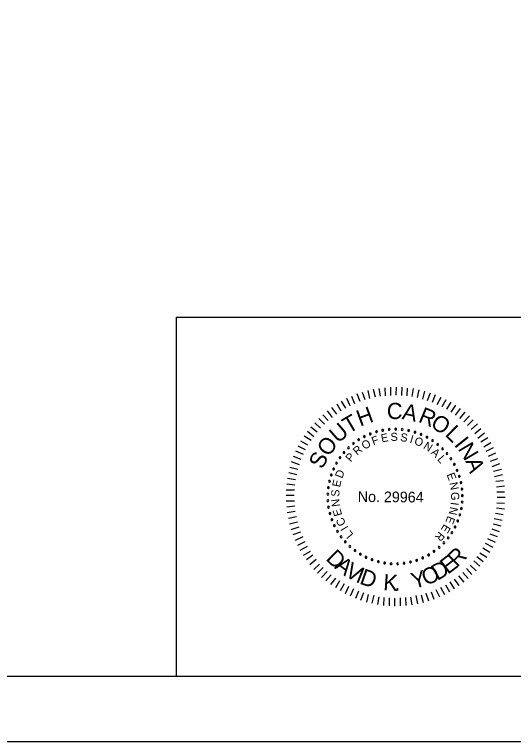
# Model space of a CAD drawing. Extents: x -121.2 to -24.9, y 6.4 to 65.7.
# Drawn here: x -64.11 to -53.92, y 6.35 to 21.19 of the extents above; entities that cross this region are included whole.
import ezdxf

# ---------------------------------------------------------------- set-up
doc = ezdxf.new("R2010")
doc.units = 0
for name, color, linetype in [('BR_BORDER LINES', 7, 'Continuous'), ('BR_TEXT', 7, 'Continuous'), ('Level 31', 7, 'Continuous')]:
    doc.layers.add(name, color=color, linetype=linetype)

msp = doc.modelspace()

# ---------------------------------------------------------------- linework, layer by layer
at = {"layer": 'BR_BORDER LINES'}
for p, q in [((-60.804, 15.017), (-46.496, 15.017)), ((-60.804, 7.683), (-60.804, 15.017)), ((-116.272, 7.683), (-26.496, 7.683))]:
    msp.add_line(p, q, dxfattribs=at)
at = {"layer": 'BR_TEXT'}
for p, q in [((-56.854, 13.352), (-56.89, 13.515)), ((-56.744, 13.379), (-56.782, 13.537)), ((-56.639, 13.398), (-56.663, 13.561)), ((-56.534, 13.409), (-56.544, 13.572)), ((-56.428, 13.415), (-56.427, 13.587)), ((-56.316, 13.421), (-56.315, 13.586)), ((-56.204, 13.413), (-56.198, 13.585)), ((-56.097, 13.405), (-56.084, 13.568)), ((-55.994, 13.393), (-55.965, 13.555)), ((-55.886, 13.372), (-55.848, 13.529)), ((-57.16, 13.247), (-57.223, 13.396)), ((-57.056, 13.292), (-57.112, 13.448)), ((-56.951, 13.326), (-57.009, 13.479)), ((-55.777, 13.343), (-55.734, 13.505)), ((-55.679, 13.315), (-55.62, 13.468)), ((-55.574, 13.28), (-55.515, 13.435)), ((-55.478, 13.233), (-55.403, 13.381)), ((-57.445, 13.092), (-57.526, 13.236)), ((-57.35, 13.155), (-57.432, 13.3)), ((-57.258, 13.202), (-57.328, 13.351)), ((-55.382, 13.187), (-55.298, 13.335)), ((-55.282, 13.138), (-55.196, 13.281)), ((-55.193, 13.073), (-55.103, 13.216)), ((-57.617, 12.967), (-57.724, 13.101)), ((-57.528, 13.035), (-57.632, 13.171)), ((-55.104, 13.015), (-55.007, 13.149)), ((-55.018, 12.946), (-54.909, 13.078)), ((-57.783, 12.829), (-57.901, 12.947)), ((-57.705, 12.902), (-57.816, 13.021)), ((-54.934, 12.879), (-54.818, 12.997)), ((-54.859, 12.805), (-54.743, 12.921)), ((-57.929, 12.663), (-58.061, 12.767)), ((-57.862, 12.747), (-57.978, 12.86)), ((-54.784, 12.722), (-54.657, 12.833)), ((-57.998, 12.574), (-58.13, 12.681)), ((-54.712, 12.636), (-54.587, 12.738)), ((-54.648, 12.547), (-54.517, 12.651)), ((-58.121, 12.399), (-58.264, 12.485)), ((-58.056, 12.497), (-58.2, 12.585)), ((-54.589, 12.468), (-54.449, 12.554)), ((-58.168, 12.308), (-58.318, 12.382)), ((-54.531, 12.37), (-54.388, 12.453)), ((-54.483, 12.278), (-54.329, 12.35)), ((-58.214, 12.21), (-58.367, 12.278)), ((-54.436, 12.179), (-54.284, 12.244)), ((-58.294, 12), (-58.458, 12.061)), ((-58.261, 12.107), (-58.416, 12.166)), ((-54.391, 12.075), (-54.24, 12.131)), ((-54.355, 11.968), (-54.202, 12.026)), ((-58.326, 11.904), (-58.489, 11.945)), ((-54.329, 11.871), (-54.168, 11.909)), ((-58.346, 11.792), (-58.512, 11.835)), ((-54.307, 11.759), (-54.146, 11.799)), ((-58.386, 11.587), (-58.551, 11.606)), ((-58.374, 11.696), (-58.536, 11.718)), ((-54.285, 11.663), (-54.127, 11.682)), ((-58.394, 11.481), (-58.566, 11.483)), ((-54.267, 11.553), (-54.105, 11.57)), ((-54.264, 11.447), (-54.103, 11.446)), ((-58.4, 11.372), (-58.567, 11.373)), ((-54.258, 11.338), (-54.095, 11.336)), ((-58.396, 11.257), (-58.568, 11.254)), ((-58.39, 11.154), (-58.555, 11.135)), ((-54.265, 11.223), (-54.105, 11.217)), ((-58.379, 11.044), (-58.542, 11.02)), ((-54.29, 11.011), (-54.132, 10.984)), ((-54.271, 11.12), (-54.109, 11.098)), ((-58.353, 10.939), (-58.52, 10.904)), ((-54.314, 10.905), (-54.154, 10.867)), ((-58.335, 10.826), (-58.498, 10.789)), ((-58.304, 10.728), (-58.469, 10.672)), ((-54.366, 10.695), (-54.213, 10.637)), ((-54.338, 10.793), (-54.178, 10.753)), ((-58.273, 10.625), (-58.429, 10.569)), ((-54.403, 10.593), (-54.253, 10.534)), ((-58.228, 10.526), (-58.382, 10.454)), ((-58.183, 10.429), (-58.335, 10.35)), ((-54.499, 10.399), (-54.346, 10.318)), ((-54.45, 10.495), (-54.3, 10.42)), ((-58.138, 10.331), (-58.283, 10.247)), ((-54.548, 10.301), (-54.407, 10.215)), ((-58.075, 10.232), (-58.22, 10.148)), ((-58.018, 10.153), (-58.152, 10.056)), ((-54.668, 10.126), (-54.539, 10.026)), ((-54.608, 10.203), (-54.469, 10.117)), ((-57.95, 10.064), (-58.084, 9.959)), ((-57.885, 9.974), (-58.002, 9.865)), ((-54.807, 9.948), (-54.682, 9.837)), ((-54.733, 10.037), (-54.61, 9.931)), ((-57.808, 9.904), (-57.927, 9.784)), ((-57.73, 9.824), (-57.844, 9.701)), ((-54.959, 9.801), (-54.846, 9.676)), ((-54.883, 9.88), (-54.77, 9.758)), ((-57.644, 9.754), (-57.753, 9.629)), ((-57.555, 9.685), (-57.662, 9.558)), ((-55.132, 9.665), (-55.037, 9.536)), ((-55.044, 9.733), (-54.938, 9.606)), ((-57.473, 9.627), (-57.557, 9.488)), ((-57.38, 9.567), (-57.464, 9.423)), ((-57.289, 9.513), (-57.361, 9.365)), ((-55.311, 9.55), (-55.228, 9.405)), ((-55.222, 9.608), (-55.134, 9.468)), ((-57.191, 9.467), (-57.256, 9.319)), ((-57.088, 9.42), (-57.147, 9.27)), ((-56.983, 9.387), (-57.044, 9.232)), ((-56.888, 9.354), (-56.925, 9.197)), ((-55.711, 9.377), (-55.655, 9.221)), ((-55.606, 9.408), (-55.55, 9.256)), ((-55.509, 9.453), (-55.437, 9.304)), ((-55.413, 9.498), (-55.331, 9.348)), ((-56.778, 9.335), (-56.818, 9.171)), ((-56.673, 9.305), (-56.699, 9.149)), ((-56.568, 9.292), (-56.58, 9.128)), ((-56.462, 9.285), (-56.464, 9.12)), ((-56.35, 9.277), (-56.352, 9.114)), ((-56.238, 9.283), (-56.235, 9.118)), ((-56.131, 9.289), (-56.121, 9.124)), ((-56.028, 9.299), (-56.001, 9.143)), ((-55.92, 9.328), (-55.884, 9.163)), ((-55.81, 9.346), (-55.77, 9.187))]:
    msp.add_line(p, q, dxfattribs=at)
for centre, start, end in [((-56.847, 12.632), 21.6807, 201.6807), ((-56.847, 12.632), 201.6807, 21.6807), ((-56.721, 12.674), 16.1422, 196.1422), ((-56.721, 12.674), 196.1422, 16.1422), ((-56.592, 12.705), 10.6038, 190.6038), ((-56.592, 12.705), 190.6038, 10.6038), ((-56.46, 12.723), 5.0653, 185.0653), ((-56.46, 12.723), 185.0653, 5.0653), ((-56.328, 12.728), 359.5268, 179.5268), ((-56.328, 12.728), 179.5268, 359.5268), ((-56.195, 12.72), 353.9884, 173.9884), ((-56.195, 12.72), 173.9884, 353.9884), ((-56.064, 12.699), 348.4499, 168.4499), ((-56.064, 12.699), 168.4499, 348.4499), ((-55.935, 12.666), 162.9114, 342.9114), ((-55.935, 12.666), 342.9114, 162.9114), ((-55.81, 12.621), 157.373, 337.373), ((-55.81, 12.621), 337.373, 157.373), ((-57.083, 12.511), 32.7576, 212.7576), ((-57.083, 12.511), 212.7576, 32.7576), ((-56.968, 12.577), 27.2191, 207.2191), ((-56.968, 12.577), 207.2191, 27.2191), ((-55.69, 12.564), 151.8345, 331.8345), ((-55.69, 12.564), 331.8345, 151.8345), ((-55.576, 12.495), 146.2961, 326.2961), ((-55.576, 12.495), 326.2961, 146.2961), ((-57.292, 12.347), 43.8345, 223.8345), ((-57.292, 12.347), 223.8345, 43.8345), ((-57.192, 12.434), 38.2961, 218.2961), ((-57.192, 12.434), 218.2961, 38.2961), ((-55.47, 12.416), 140.7576, 320.7576), ((-55.47, 12.416), 320.7576, 140.7576), ((-55.371, 12.327), 135.2191, 315.2191), ((-55.371, 12.327), 315.2191, 135.2191), ((-57.384, 12.25), 49.373, 229.373), ((-57.384, 12.25), 229.373, 49.373), ((-55.282, 12.229), 129.6807, 309.6807), ((-55.282, 12.229), 309.6807, 129.6807), ((-57.537, 12.033), 60.4499, 240.4499), ((-57.537, 12.033), 240.4499, 60.4499), ((-57.465, 12.145), 54.9114, 234.9114), ((-57.465, 12.145), 234.9114, 54.9114), ((-55.202, 12.122), 124.1422, 304.1422), ((-55.202, 12.122), 304.1422, 124.1422), ((-55.133, 12.009), 118.6038, 298.6038), ((-55.133, 12.009), 298.6038, 118.6038), ((-57.597, 11.915), 65.9884, 245.9884), ((-57.597, 11.915), 245.9884, 65.9884), ((-55.075, 11.889), 113.0653, 293.0653), ((-55.075, 11.889), 293.0653, 113.0653), ((-57.645, 11.791), 71.5268, 251.5268), ((-57.645, 11.791), 251.5268, 71.5268), ((-55.029, 11.764), 107.5268, 287.5268), ((-55.029, 11.764), 287.5268, 107.5268), ((-57.681, 11.663), 77.0653, 257.0653), ((-57.681, 11.663), 257.0653, 77.0653), ((-54.996, 11.636), 101.9884, 281.9884), ((-54.996, 11.636), 281.9884, 101.9884), ((-57.705, 11.532), 82.6038, 262.6038), ((-57.705, 11.532), 262.6038, 82.6038), ((-54.975, 11.504), 96.4499, 276.4499), ((-54.975, 11.504), 276.4499, 96.4499), ((-57.716, 11.4), 88.1422, 268.1422), ((-57.714, 11.267), 93.6807, 273.6807), ((-57.716, 11.4), 268.1422, 88.1422), ((-57.714, 11.267), 273.6807, 93.6807), ((-54.967, 11.372), 90.9114, 270.9114), ((-54.967, 11.372), 270.9114, 90.9114), ((-57.7, 11.135), 99.2191, 279.2191), ((-57.7, 11.135), 279.2191, 99.2191), ((-54.971, 11.239), 85.373, 265.373), ((-54.971, 11.239), 265.373, 85.373), ((-57.672, 11.005), 104.7576, 284.7576), ((-57.672, 11.005), 284.7576, 104.7576), ((-55.019, 10.978), 74.2961, 254.2961), ((-55.019, 10.978), 254.2961, 74.2961), ((-54.989, 11.107), 79.8345, 259.8345), ((-54.989, 11.107), 259.8345, 79.8345), ((-57.632, 10.878), 110.2961, 290.2961), ((-57.632, 10.878), 290.2961, 110.2961), ((-55.061, 10.852), 68.7576, 248.7576), ((-55.061, 10.852), 248.7576, 68.7576), ((-57.581, 10.756), 115.8345, 295.8345), ((-57.581, 10.756), 295.8345, 115.8345), ((-55.115, 10.731), 63.2191, 243.2191), ((-55.115, 10.731), 243.2191, 63.2191), ((-57.517, 10.639), 121.373, 301.373), ((-57.517, 10.639), 301.373, 121.373), ((-57.443, 10.529), 126.9114, 306.9114), ((-57.443, 10.529), 306.9114, 126.9114), ((-55.181, 10.615), 57.6807, 237.6807), ((-55.181, 10.615), 237.6807, 57.6807), ((-57.358, 10.426), 132.4499, 312.4499), ((-57.358, 10.426), 312.4499, 132.4499), ((-55.344, 10.406), 46.6038, 226.6038), ((-55.344, 10.406), 226.6038, 46.6038), ((-55.258, 10.507), 52.1422, 232.1422), ((-55.258, 10.507), 232.1422, 52.1422), ((-57.264, 10.333), 137.9884, 317.9884), ((-57.264, 10.333), 317.9884, 137.9884), ((-57.161, 10.248), 143.5268, 323.5268), ((-57.161, 10.248), 323.5268, 143.5268), ((-55.545, 10.232), 35.5268, 215.5268), ((-55.545, 10.232), 215.5268, 35.5268), ((-55.44, 10.314), 41.0653, 221.0653), ((-55.44, 10.314), 221.0653, 41.0653), ((-57.051, 10.174), 149.0653, 329.0653), ((-57.051, 10.174), 329.0653, 149.0653), ((-56.934, 10.112), 154.6038, 334.6038), ((-56.934, 10.112), 334.6038, 154.6038), ((-55.775, 10.1), 24.4499, 204.4499), ((-55.775, 10.1), 204.4499, 24.4499), ((-55.657, 10.16), 29.9884, 209.9884), ((-55.657, 10.16), 209.9884, 29.9884), ((-56.811, 10.06), 160.1422, 340.1422), ((-56.811, 10.06), 340.1422, 160.1422), ((-56.684, 10.021), 345.6807, 165.6807), ((-56.684, 10.021), 165.6807, 345.6807), ((-56.554, 9.994), 351.2191, 171.2191), ((-56.554, 9.994), 171.2191, 351.2191), ((-56.422, 9.98), 356.7576, 176.7576), ((-56.422, 9.98), 176.7576, 356.7576), ((-56.289, 9.978), 2.2961, 182.2961), ((-56.289, 9.978), 182.2961, 2.2961), ((-56.157, 9.99), 7.8345, 187.8345), ((-56.157, 9.99), 187.8345, 7.8345), ((-56.026, 10.014), 13.373, 193.373), ((-56.026, 10.014), 193.373, 13.373), ((-55.899, 10.051), 18.9114, 198.9114), ((-55.899, 10.051), 198.9114, 18.9114)]:
    msp.add_arc(centre, 0.0187, start, end, dxfattribs=at)
at = {"layer": 'Level 31'}
msp.add_lwpolyline([(-121.161, 6.35), (-25.161, 6.35), (-25.161, 65.017), (-121.161, 65.017)], close=True, dxfattribs=at)

# ---------------------------------------------------------------- texts
at = {"layer": 'BR_TEXT'}
for s, height, rotation, p in [('C', 0.331, 359.5482, (-56.51, 12.935)), ('A', 0.331, 348.1981, (-56.213, 12.937)), ('H', 0.331, 20.3637, (-57.055, 12.779)), ('R', 0.331, 337.4344, (-55.884, 12.884)), ('T', 0.331, 30.4992, (-57.29, 12.626)), ('O', 0.33, 326.5869, (-55.638, 12.786)), ('U', 0.331, 40.8022, (-57.506, 12.426)), ('L', 0.331, 315.9488, (-55.338, 12.605)), ('E', 0.166, 11.4103, (-56.611, 12.456)), ('S', 0.166, 2.208, (-56.431, 12.485)), ('S', 0.166, 352.6608, (-56.241, 12.485)), ('O', 0.331, 52.0267, (-57.705, 12.149)), ('O', 0.166, 30.8477, (-56.965, 12.302)), ('F', 0.166, 20.6127, (-56.785, 12.398)), ('I', 0.166, 343.1136, (-56.053, 12.453)), ('O', 0.166, 338.4392, (-55.964, 12.426)), ('N', 0.166, 328.2042, (-55.778, 12.342)), ('I', 0.331, 308.6613, (-55.148, 12.407)), ('R', 0.166, 40.3949, (-57.115, 12.185)), ('N', 0.331, 300.7037, (-55.066, 12.329)), ('S', 0.33, 63.2511, (-57.826, 11.894)), ('P', 0.166, 49.9421, (-57.243, 12.045)), ('A', 0.166, 318.657, (-55.621, 12.235)), ('L', 0.166, 309.4546, (-55.488, 12.109)), ('A', 0.331, 289.4792, (-54.908, 12.081)), ('D', 0.166, 69.0364, (-57.421, 11.711)), ('E', 0.166, 291.049, (-55.291, 11.801)), ('E', 0.166, 78.2388, (-57.466, 11.533)), ('N', 0.166, 281.8466, (-55.232, 11.628)), ('S', 0.166, 87.786, (-57.481, 11.344)), ('No. 29964', 0.218, 359.5268, (-57.104, 11.241)), ('G', 0.166, 272.2995, (-55.201, 11.441)), ('N', 0.166, 97.3332, (-57.464, 11.154)), ('N', 0.166, 257.7339, (-55.214, 11.151)), ('I', 0.166, 262.4084, (-55.202, 11.244)), ('E', 0.166, 106.5355, (-57.419, 10.977)), ('C', 0.166, 116.4266, (-57.339, 10.797)), ('E', 0.166, 248.1867, (-55.262, 10.968)), ('I', 0.166, 121.1011, (-57.291, 10.717)), ('E', 0.166, 238.9844, (-55.337, 10.8)), ('L', 0.166, 129.9595, (-57.183, 10.578)), ('R', 0.166, 229.782, (-55.437, 10.647)), ('D', 0.329, 315.4053, (-57.771, 10.07)), ('R', 0.329, 44.5947, (-55.075, 9.895)), ('E', 0.329, 37.5339, (-55.263, 9.751)), ('A', 0.329, 322.8377, (-57.593, 9.895)), ('V', 0.329, 330.5179, (-57.387, 9.739)), ('D', 0.329, 30.1015, (-55.479, 9.626)), ('I', 0.329, 338.1981, (-57.163, 9.613)), ('D', 0.329, 340.7995, (-57.083, 9.577)), ('Y', 0.329, 14.8649, (-55.962, 9.462)), ('O', 0.329, 22.4212, (-55.717, 9.527)), ('K', 0.329, 356.098, (-56.589, 9.442)), ('.', 0.329, 3.1588, (-56.353, 9.426))]:
    msp.add_text(s, height=height, rotation=rotation, dxfattribs=at).set_placement(p)

doc.saveas('drawing.dxf')
